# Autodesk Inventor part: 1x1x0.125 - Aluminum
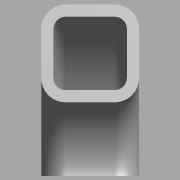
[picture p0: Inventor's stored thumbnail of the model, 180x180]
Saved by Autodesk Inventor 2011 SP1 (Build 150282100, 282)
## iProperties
Created: 2011-03
Part Number: 1x1x0.125 - Aluminum
Material: Default
Document SubType Name: Modeling
Designer: bamfomg
Density: 1 g/cm^3
Author: bamfomg
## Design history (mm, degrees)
derived "Square Tube Corners.ipt" dims "d2" = 12.7, "d3" = 12.7, "d6" = 3.175, "d7" = 3.175, "d8" = 3.175, "d12" = 90 deg, "d16" = 1.5875, "d18" = 30 deg, "ID_Rad" = 3.175, "OD_Rad" = 6.35, "Side_One" = 25.4, "Side_Two" = 25.4, "Thickness" = 3.175, "Bend_IDRad" = 19.05, "Bevel_Angl" = 30 deg, "Bevel_Dist" = 1.5875
body "Solid1"
feature "Solid1::Square Tube Corners.ipt" dims "d2" = 12.7, "d3" = 12.7, "d6" = 3.175, "d7" = 3.175, "d8" = 3.175, "d12" = 90 deg, "d16" = 1.5875, "d18" = 30 deg, "ID_Rad" = 3.175, "OD_Rad" = 6.35, "Side_One" = 25.4, "Side_Two" = 25.4, "Thickness" = 3.175, "Bend_IDRad" = 19.05, "Bevel_Angl" = 30 deg, "Bevel_Dist" = 1.5875, "ScaleForDerivedMember" = 10
tag "TaggingFeature1"
